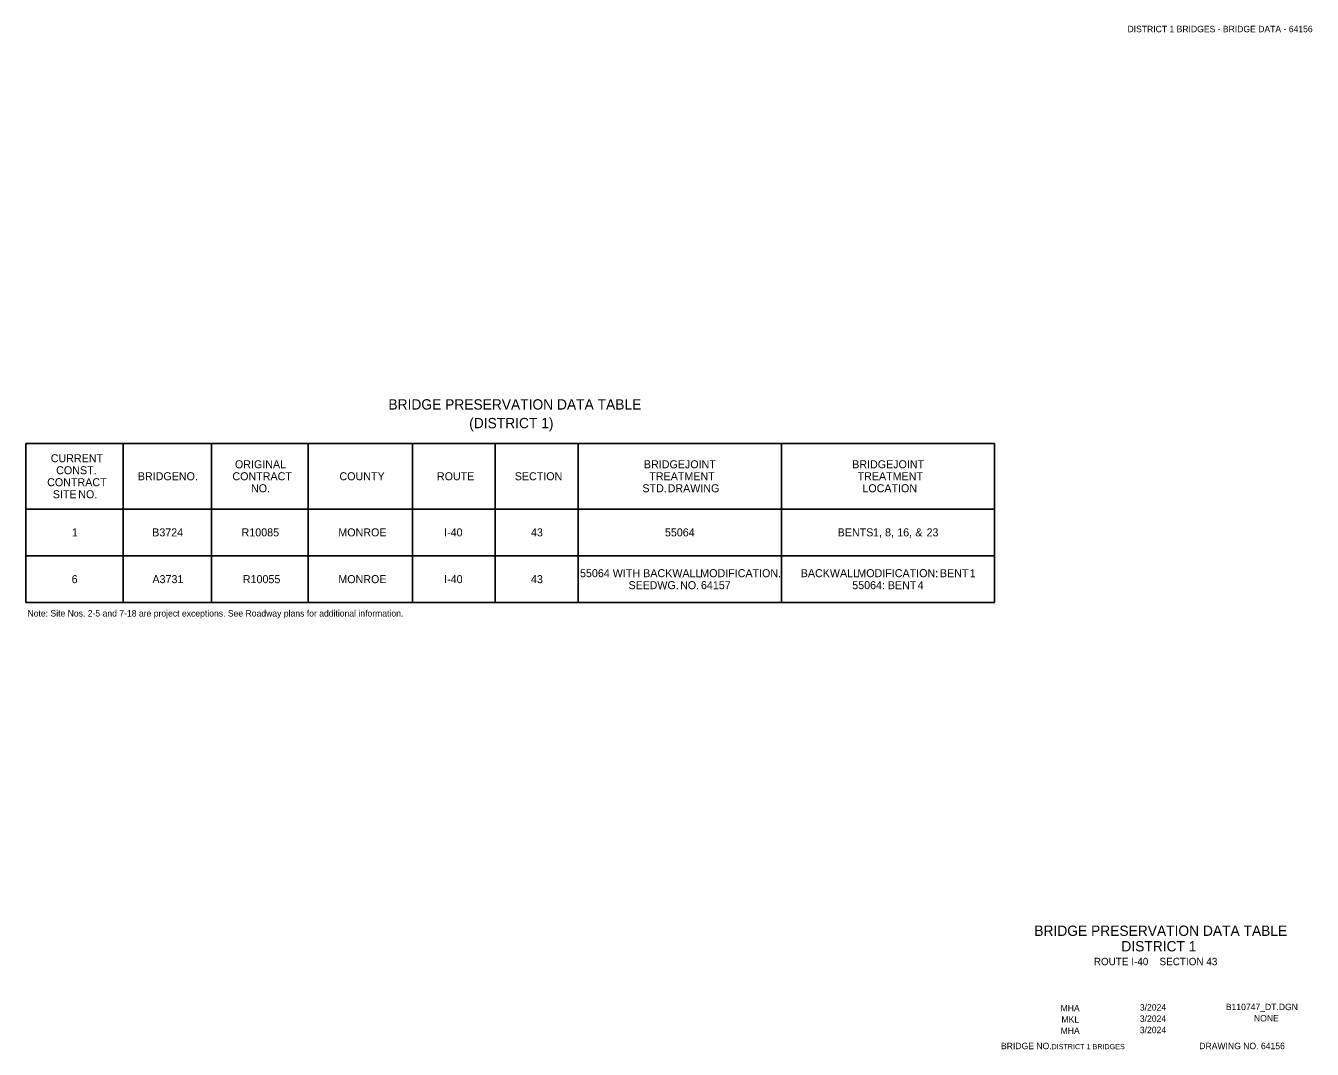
# Model space of a CAD drawing. Extents: x 195.9 to 220.9, y 129.3 to 149.2.
import ezdxf

# ---------------------------------------------------------------- set-up
doc = ezdxf.new("R2010")
doc.units = 0
for name, color, linetype in [('B_Copy In', 7, 'Continuous'), ('B_Text', 7, 'Continuous'), ('B_Title Text', 7, 'Continuous'), ('E_No Plot', 7, 'Continuous')]:
    doc.layers.add(name, color=color, linetype=linetype)

msp = doc.modelspace()

# ---------------------------------------------------------------- linework, layer by layer
at = {"layer": 'B_Text'}
for p, q in [((195.861, 141.039), (214.685, 141.039)), ((195.861, 137.947), (195.861, 141.039)), ((197.755, 137.947), (197.755, 141.039)), ((199.468, 137.947), (199.468, 141.039)), ((201.347, 137.947), (201.347, 141.039)), ((203.378, 137.947), (203.378, 141.039)), ((204.985, 137.947), (204.985, 141.039)), ((206.592, 137.947), (206.592, 141.039)), ((210.548, 137.947), (210.548, 141.039)), ((214.685, 137.947), (214.685, 141.039)), ((195.861, 139.765), (214.685, 139.765)), ((195.861, 138.856), (214.685, 138.856)), ((195.861, 137.947), (214.685, 137.947))]:
    msp.add_line(p, q, dxfattribs=at)
at = {"layer": 'E_No Plot'}
msp.add_line((195.861, 141.039), (195.861, 141.039), dxfattribs=at)

# ---------------------------------------------------------------- texts
at = {"layer": 'B_Copy In'}
for s, height, p in [('DISTRICT 1 BRIDGES - BRIDGE DATA - 64156', 0.1248, (217.269, 149.033)), ('BRIDGE PRESERVATION DATA TABLE', 0.2004, (215.459, 131.467)), ('DISTRICT 1', 0.2004, (217.15, 131.166)), ('ROUTE I-40', 0.144, (216.615, 130.897)), ('SECTION 43', 0.144, (217.892, 130.897)), ('MHA', 0.125, (215.969, 130.001)), ('3/2024', 0.125, (217.509, 130.016)), ('B110747_DT.DGN', 0.1248, (219.18, 130.024)), ('MKL', 0.125, (215.986, 129.781)), ('3/2024', 0.125, (217.509, 129.796)), ('NONE', 0.125, (219.726, 129.805)), ('MHA', 0.125, (215.969, 129.561)), ('3/2024', 0.125, (217.509, 129.576)), ('BRIDGE NO. ', 0.125, (214.811, 129.265)), ('DISTRICT 1 BRIDGES', 0.1008, (215.793, 129.265)), ('DRAWING NO. 64156', 0.125, (218.664, 129.265))]:
    msp.add_text(s, height=height, dxfattribs=at).set_placement(p)
at = {"layer": 'B_Text'}
for s, height, p in [('(DISTRICT 1)', 0.2004, (204.478, 141.335)), ('CURRENT', 0.1555, (196.347, 140.674)), ('CONST.', 0.1555, (196.452, 140.441)), ('ORIGINAL', 0.1555, (199.926, 140.557)), ('BRIDGE', 0.1555, (207.873, 140.557)), (' JOINT', 0.1555, (208.612, 140.557)), ('BRIDGE', 0.1555, (211.92, 140.557)), (' JOINT', 0.1555, (212.659, 140.557)), ('CONTRACT', 0.1555, (196.277, 140.208)), ('BRIDGE', 0.1555, (198.039, 140.324)), (' NO.', 0.1555, (198.778, 140.324)), ('CONTRACT', 0.1555, (199.877, 140.324)), ('NO.', 0.1555, (200.238, 140.091)), ('COUNTY', 0.1555, (201.957, 140.324)), ('ROUTE', 0.1555, (203.851, 140.324)), ('SECTION', 0.1555, (205.363, 140.324)), ('STD.', 0.1555, (207.843, 140.091)), ('TREATMENT', 0.1555, (207.978, 140.324)), (' DRAWING', 0.1555, (208.276, 140.091)), ('TREATMENT', 0.1555, (212.025, 140.324)), ('LOCATION', 0.1555, (212.118, 140.091)), ('SITE', 0.1555, (196.387, 139.974)), (' NO.', 0.1555, (196.824, 139.974)), ('1', 0.155, (196.758, 139.233)), ('B3724', 0.1555, (198.318, 139.233)), ('R10085', 0.1555, (200.055, 139.233)), ('MONROE', 0.1555, (201.935, 139.233)), ('I-40', 0.1555, (203.991, 139.233)), ('43', 0.1555, (205.678, 139.233)), ('55064', 0.1555, (208.281, 139.233)), ('BENTS', 0.1555, (211.638, 139.233)), (' 1,', 0.1555, (212.266, 139.233)), (' 8,', 0.1555, (212.501, 139.233)), (' 16,', 0.1555, (212.737, 139.233)), (' &', 0.1555, (213.089, 139.233)), (' 23', 0.1555, (213.307, 139.233)), ('55064', 0.1555, (206.631, 138.44)), (' WITH', 0.1555, (207.209, 138.44)), (' BACKWALL', 0.1555, (207.801, 138.44)), (' MODIFICATION.', 0.15545, (208.91, 138.44)), ('BACKWALL', 0.1555, (210.92, 138.44)), (' MODIFICATION:', 0.15545, (211.962, 138.44)), (' BENT', 0.1555, (213.566, 138.44)), (' 1', 0.1555, (214.146, 138.44)), ('6', 0.155, (196.753, 138.324)), ('A3731', 0.1555, (198.323, 138.324)), (' R10055', 0.1555, (200.022, 138.324)), ('MONROE', 0.1555, (201.935, 138.324)), ('I-40', 0.1555, (203.991, 138.324)), ('43', 0.1555, (205.678, 138.324)), ('SEE', 0.1555, (207.574, 138.207)), (' DWG.', 0.1555, (207.926, 138.207)), (' NO.', 0.1555, (208.518, 138.207)), (' 64157', 0.1555, (208.923, 138.207)), ('55064:', 0.1555, (211.921, 138.207)), (' BENT', 0.1555, (212.554, 138.207)), (' 4', 0.1555, (213.134, 138.207)), ('Note: Site Nos. 2-5 and 7-18 are project exceptions. See Roadway plans for additional information. ', 0.125, (195.895, 137.675))]:
    msp.add_text(s, height=height, dxfattribs=at).set_placement(p)
at = {"layer": 'B_Title Text'}
msp.add_text('BRIDGE PRESERVATION DATA TABLE', height=0.2004, dxfattribs=at).set_placement((202.908, 141.698))

doc.saveas('drawing.dxf')
